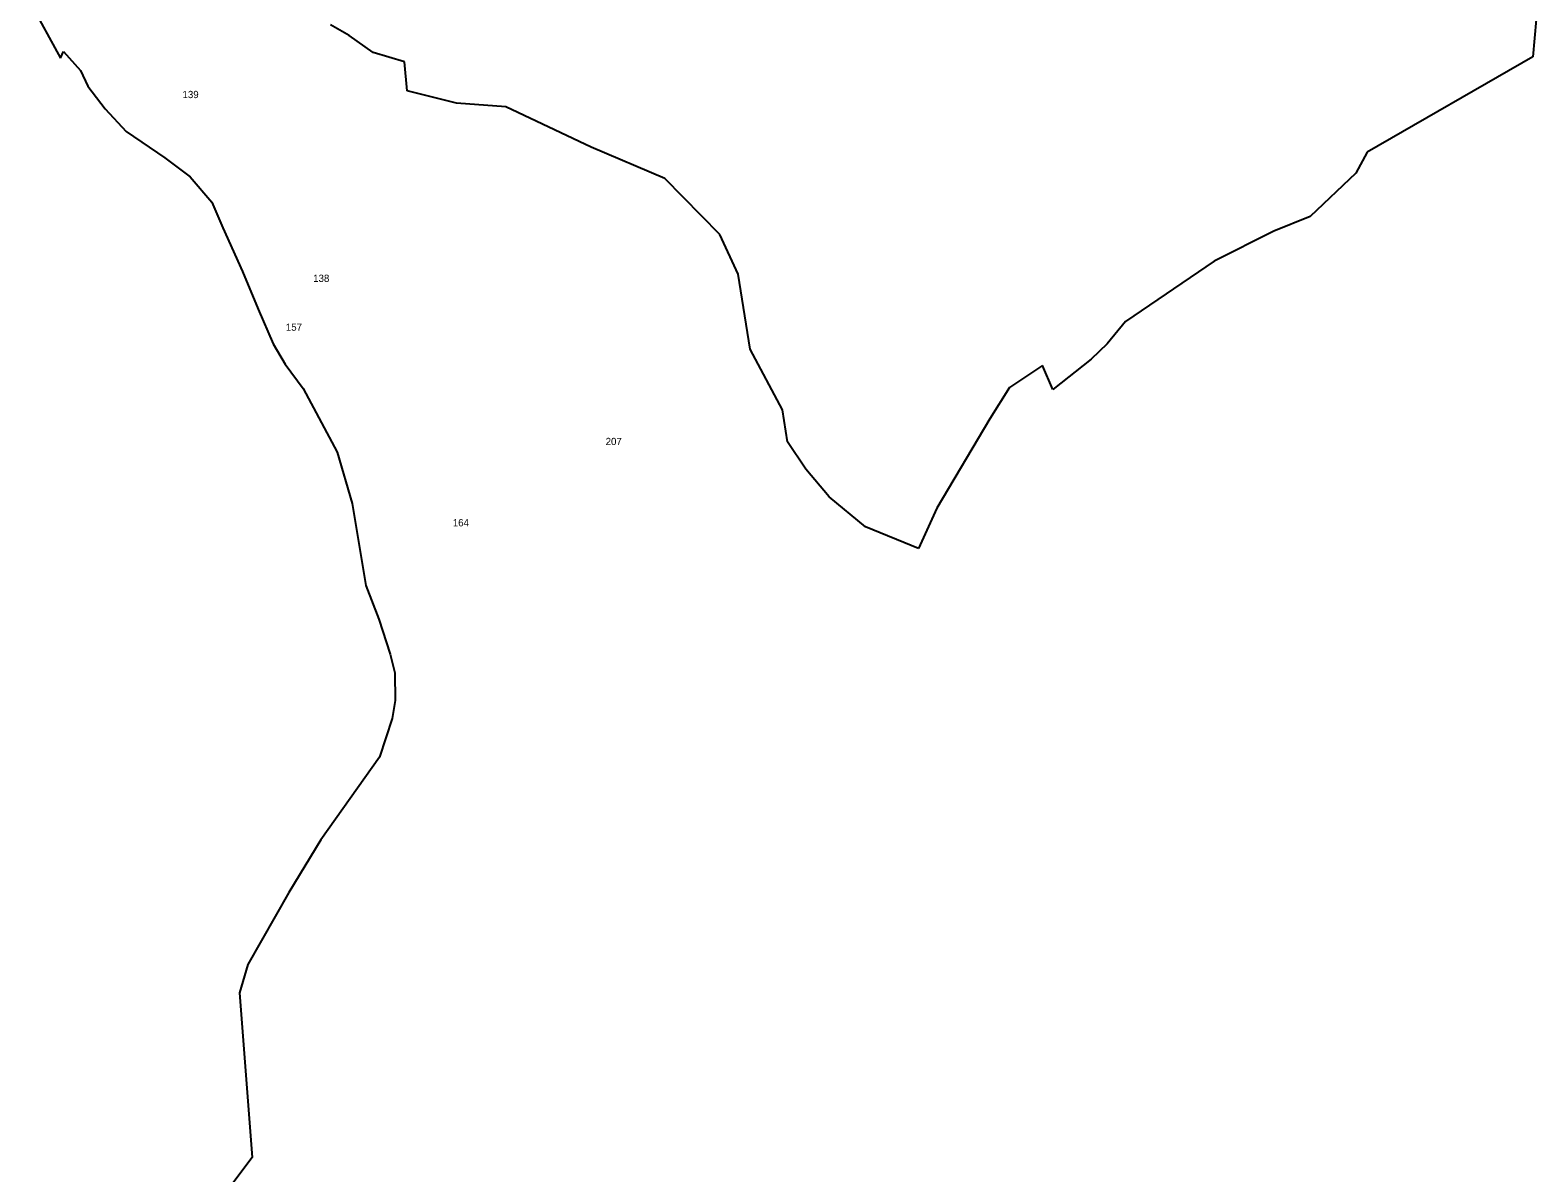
# Model space of a CAD drawing. Extents: x -787692 to -782531, y -972586 to -966265.
# Drawn here: x -787692 to -785611, y -969423 to -967846 of the extents above; entities that cross this region are included whole.
import ezdxf

# ---------------------------------------------------------------- set-up
doc = ezdxf.new("R2010")
doc.units = 0
doc.layers.add('Vrstva 13', color=7, linetype='Continuous')
doc.layers.add('Vrstva 24', color=7, linetype='Continuous')

msp = doc.modelspace()

# ---------------------------------------------------------------- linework, layer by layer
at = {"layer": 'Vrstva 13'}
for p, q in [((-787692.02, -967808.05), (-787650.12, -967884.42)), ((-785611.11, -967805.28), (-785618.22, -967882.5)), ((-787251.77, -967853.26), (-787277.63, -967838.27)), ((-787218.8, -967876.5), (-787251.77, -967853.26)), ((-787650.12, -967884.42), (-787645.81, -967875.23)), ((-787645.81, -967875.23), (-787622.57, -967901.36)), ((-787175.34, -967889.62), (-787218.8, -967876.5)), ((-787171.6, -967929.72), (-787175.34, -967889.62)), ((-785618.22, -967882.5), (-785846.77, -968014.06)), ((-787622.57, -967901.36), (-787612.52, -967923.18)), ((-787612.52, -967923.18), (-787588.7, -967954.18)), ((-787103.78, -967946.59), (-787171.6, -967929.72)), ((-787588.7, -967954.18), (-787559.43, -967985.76)), ((-787035.59, -967951.46), (-787103.78, -967946.59)), ((-786917.94, -968007.3), (-787035.59, -967951.46)), ((-787559.43, -967985.76), (-787506.05, -968022.23)), ((-786816.03, -968050.41), (-786917.94, -968007.3)), ((-785846.77, -968014.06), (-785862.5, -968043.09)), ((-787506.05, -968022.23), (-787471.33, -968048.07)), ((-787471.33, -968048.07), (-787441.48, -968083.09)), ((-786739.98, -968127.61), (-786816.03, -968050.41)), ((-785862.5, -968043.09), (-785925.44, -968103.06)), ((-787441.48, -968083.09), (-787425.98, -968118.69)), ((-787425.98, -968118.69), (-787399, -968178.98)), ((-785925.44, -968103.06), (-785975.65, -968123.29)), ((-786714.87, -968182.72), (-786739.98, -968127.61)), ((-785975.65, -968123.29), (-786058.07, -968164.52)), ((-787399, -968178.98), (-787377.19, -968230.95)), ((-786698.39, -968286.16), (-786714.87, -968182.72)), ((-786058.07, -968164.52), (-786180.21, -968247.73)), ((-787377.19, -968230.95), (-787356.82, -968278.89)), ((-786180.21, -968247.73), (-786205.33, -968278.66)), ((-787356.82, -968278.89), (-787340.17, -968307.03)), ((-786653.43, -968369.74), (-786698.39, -968286.16)), ((-786205.33, -968278.66), (-786227.81, -968300.02)), ((-787340.17, -968307.03), (-787315.21, -968340.62)), ((-786294.87, -968308.64), (-786340.21, -968339)), ((-786280.64, -968342), (-786294.87, -968308.64)), ((-786227.81, -968300.02), (-786280.64, -968342)), ((-787315.21, -968340.62), (-787268.43, -968428.18)), ((-786340.21, -968339), (-786367.56, -968382.48)), ((-786646.69, -968413.97), (-786653.43, -968369.74)), ((-786367.56, -968382.48), (-786440.62, -968505.42)), ((-787268.43, -968428.18), (-787247.48, -968499.1)), ((-786621.21, -968451.83), (-786646.69, -968413.97)), ((-786589.37, -968490.06), (-786621.21, -968451.83)), ((-786539.16, -968531.28), (-786589.37, -968490.06)), ((-787247.48, -968499.1), (-787228.83, -968612.21)), ((-786440.62, -968505.42), (-786466.1, -968561.26)), ((-786466.1, -968561.26), (-786539.16, -968531.28)), ((-787228.83, -968612.21), (-787210.76, -968658.72)), ((-787210.76, -968658.72), (-787195.26, -968706.95)), ((-787195.26, -968706.95), (-787188.66, -968733.08)), ((-787188.66, -968733.08), (-787188.37, -968770.98)), ((-787188.37, -968770.98), (-787192.38, -968795.67)), ((-787192.38, -968795.67), (-787209.89, -968849.07)), ((-787209.89, -968849.07), (-787290.81, -968963.32)), ((-787290.81, -968963.32), (-787335.01, -969036.24)), ((-787335.01, -969036.24), (-787391.69, -969135.44)), ((-787391.69, -969135.44), (-787403.17, -969174.48)), ((-787403.17, -969174.48), (-787385.38, -969401.86)), ((-787385.38, -969401.86), (-787437.61, -969470.76))]:
    msp.add_line(p, q, dxfattribs=at)

# ---------------------------------------------------------------- texts
at = {"layer": 'Vrstva 24'}
for s, p in [('139', (-787481.744, -967939.56)), ('138', (-787301.381, -968193.24)), ('157', (-787339.1, -968260.68)), ('207', (-786897.745, -968418.49)), ('164', (-787108.69, -968530.64))]:
    msp.add_text(s, height=10, dxfattribs=at).set_placement(p)

doc.saveas('drawing.dxf')
